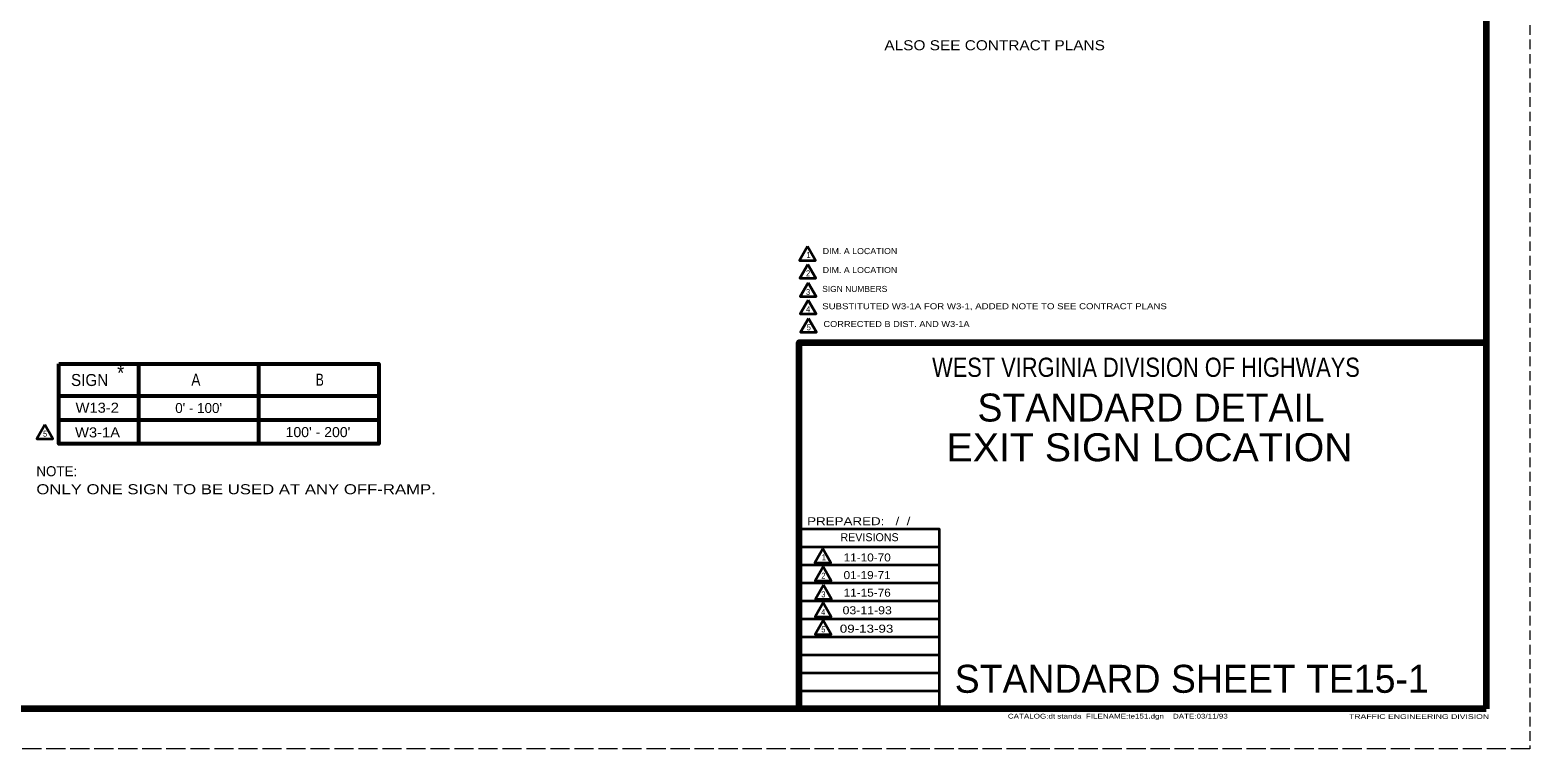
# Model space of a CAD drawing. Extents: x -281 to 399, y -258 to 182.
# Drawn here: x 24.5 to 399.4, y -258.5 to -78.8 of the extents above; entities that cross this region are included whole.
import ezdxf
from ezdxf.enums import TextEntityAlignment as Align

# ---------------------------------------------------------------- set-up
doc = ezdxf.new("R2010")
doc.units = 0
doc.header["$LTSCALE"] = 0.8
doc.linetypes.add('LONG_DASHED', pattern=[7.5, 6, -1.5])
doc.linetypes.add('MEDIUM_DASHED', pattern=[4.5, 3, -1.5])
doc.layers.add('1', color=7, linetype='Continuous', lineweight=53)
doc.layers.add('61', color=7, linetype='Continuous', lineweight=35)

msp = doc.modelspace()

# ---------------------------------------------------------------- linework, layer by layer
at = {"layer": '1', "linetype": 'MEDIUM_DASHED', "lineweight": 13}
msp.add_line((399.3899, 181.553), (399.3699, -258.467), dxfattribs=at)
at = {"layer": '1'}
for p, q in [((51.6653, -182.2621), (51.6653, -162.2621)), ((81.6653, -182.2621), (81.6653, -162.2621)), ((31.6653, -170.2621), (111.6653, -170.2621)), ((31.6653, -176.2621), (111.6653, -176.2621))]:
    msp.add_line(p, q, dxfattribs=at)
at = {"layer": '1', "lineweight": 35}
for p, q in [((251.7699, -208.047), (216.7899, -208.047)), ((251.7699, -212.547), (216.7899, -212.547)), ((251.7699, -217.047), (216.7899, -217.047)), ((251.7699, -221.567), (216.7899, -221.567)), ((251.7699, -226.047), (216.7899, -226.047)), ((251.7699, -230.527), (216.7899, -230.527)), ((251.7699, -235.027), (216.7899, -235.027)), ((251.7699, -239.527), (216.7899, -239.527)), ((251.7699, -244.047), (216.7899, -244.047))]:
    msp.add_line(p, q, dxfattribs=at)
for points in [[(218.8283, -132.9371), (216.8283, -136.4012), (220.8283, -136.4012)], [(218.9226, -137.4221), (216.9226, -140.8862), (220.9226, -140.8862)], [(218.9877, -142.0028), (216.9877, -145.4669), (220.9877, -145.4669)], [(218.9877, -146.3307), (216.9877, -149.7948), (220.9877, -149.7948)], [(219.0967, -150.9158), (217.0967, -154.3798), (221.0967, -154.3798)], [(28.2295, -177.519), (26.2295, -180.9831), (30.2295, -180.9831)], [(222.6617, -208.4988), (220.6617, -211.9628), (224.6617, -211.9628)], [(222.7559, -212.9837), (220.7559, -216.4478), (224.7559, -216.4478)], [(222.821, -217.5645), (220.821, -221.0286), (224.821, -221.0286)], [(222.7533, -221.9958), (220.7533, -225.4599), (224.7533, -225.4599)], [(222.7479, -226.4001), (220.7479, -229.8642), (224.7479, -229.8642)]]:
    msp.add_lwpolyline(points, close=True, dxfattribs=at)
at = {"layer": '1', "lineweight": 158}
msp.add_lwpolyline([(216.7699, -248.487), (216.7699, -156.907), (388.4299, -156.907)], dxfattribs=at)
at = {"layer": '1'}
msp.add_lwpolyline([(31.6653, -162.2621), (111.6653, -162.2621), (111.6653, -182.2621), (31.6653, -182.2621)], close=True, dxfattribs=at)
at = {"layer": '1', "lineweight": 35}
msp.add_lwpolyline([(251.7699, -248.527), (251.7699, -203.567), (216.7899, -203.567)], dxfattribs=at)
at = {"layer": '61', "lineweight": 158}
for p, q in [((388.4099, 171.553), (388.4299, -248.487)), ((388.4299, -248.487), (-250.6301, -248.467))]:
    msp.add_line(p, q, dxfattribs=at)
at = {"layer": '61', "linetype": 'LONG_DASHED', "lineweight": 13}
msp.add_line((399.3699, -258.467), (-280.6901, -258.487), dxfattribs=at)

# ---------------------------------------------------------------- texts
at = {"layer": '1'}
for s, height, width, p in [('ALSO SEE CONTRACT PLANS', 2.5, 1.15, (265.5904, -83.8967)), ('WEST VIRGINIA DIVISION OF HIGHWAYS', 4.795, 0.85, (303.4183, -165.507)), ('SIGN', 3, 0.95, (39.4025, -167.7916)), ('*', 4, 0.85, (47.1632, -166.541)), ('A', 3, 0.85, (65.9568, -167.7154)), ('B', 3, 0.75, (96.9241, -167.7154)), ('W13-2', 2.5, 1.1, (41.3045, -174.4677)), ('W3-1A', 2.5, 1.1, (41.3807, -180.6327)), ("100' - 200'", 2.5, 1.05, (96.4677, -180.5567)), ('EXIT SIGN LOCATION', 6.993, 1.05, (304.32, -186.598)), ('11-10-70', 2, 1.1, (233.7392, -211.627)), ('01-19-71', 2, 1.1, (233.7192, -216.027)), ('11-15-76', 2, 1.1, (233.7392, -220.427)), ('03-11-93', 2, 1.15, (233.7392, -224.827)), ('09-13-93', 2, 1.25, (233.5793, -229.427))]:
    msp.add_text(s, height=height, dxfattribs=dict(at, width=width)).set_placement(p, align=Align.CENTER)
for s, height, p in [('1', 1.5, (218.5097, -135.7921)), ('NOTE:', 2.5, (26.0872, -190.3312)), ('REVISIONS', 1.998, (227.0499, -206.567)), ('1', 1.5, (222.343, -211.3537)), ('STANDARD SHEET TE15-1', 6.993, (255.6099, -244.447))]:
    msp.add_text(s, height=height, dxfattribs=at).set_placement(p)
for s, height, width, p in [('DIM. A LOCATION', 1.5, 1.1, (222.6232, -134.835)), ('DIM. A LOCATION', 1.5, 1.1, (222.6232, -139.5559)), ('2', 1.5, 0.9, (218.4459, -140.3853)), ('3', 1.5, 0.9, (218.4459, -145.0425)), ('SIGN NUMBERS', 1.5, 1.05, (222.4956, -144.2768)), ('4', 1.5, 0.95, (218.4459, -149.3704)), ('SUBSTITUTED W3-1A FOR W3-1, ADDED NOTE TO SEE CONTRACT PLANS', 1.5, 1.2, (222.4956, -148.6047)), ('5', 1.5, 0.9, (218.62, -153.879)), ('CORRECTED B DIST. AND W3-1A', 1.5, 1.15, (222.7972, -153.0496)), ('5', 1.5, 0.9, (27.7528, -180.4822)), ('ONLY ONE SIGN TO BE USED AT ANY OFF-RAMP.', 2.5, 1.25, (26.0872, -194.8312)), ('PREPARED:   /  /  ', 1.998, 1.25, (218.7299, -202.567)), ('2', 1.5, 0.9, (222.2792, -215.947)), ('3', 1.5, 0.9, (222.2792, -220.6042)), ('4', 1.5, 0.95, (222.2116, -225.0355)), ('5', 1.5, 0.9, (222.2712, -229.3633)), ('CATALOG:dt standa  FILENAME:te151.dgn    DATE:03/11/93', 1.2, 1.25, (268.8899, -250.887)), ('TRAFFIC ENGINEERING DIVISION', 1.2, 1.35, (354.1499, -250.987))]:
    msp.add_text(s, height=height, dxfattribs=dict(at, width=width)).set_placement(p)
for s, height, p in [("0' - 100'", 2.5, (66.6415, -174.5438)), ('STANDARD DETAIL', 6.993, (304.6869, -176.667))]:
    msp.add_text(s, height=height, dxfattribs=at).set_placement(p, align=Align.CENTER)

doc.saveas('drawing.dxf')
